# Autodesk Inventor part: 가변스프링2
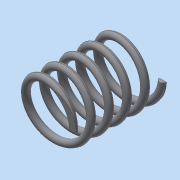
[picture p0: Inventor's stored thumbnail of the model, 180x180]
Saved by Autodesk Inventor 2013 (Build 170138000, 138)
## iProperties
Created: 2018-10
Part Number: 가변스프링2
Material: 일반
Document SubType Name: Modeling
Designer: Administrator
Density: 1 g/cm^3
Author: Administrator
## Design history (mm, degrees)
sketch "스케치1"
  geometry: L1 (0, 0)-(0, 25.765); L2 (0, 0)-(8, 0); L3 (0, 25.765)-(8, 25.765); C1 r 1 at (8, 0)
  constraints: 6 end point, 1 centre point, 1 horizontal alignment, 1 parallel, 1 perpendicular, 1 vertical
  dimensions: "d0" = 25.76498 distance of L1.start L1.end (derived); "d1" = 2 diameter of C1; "d2" = 16 diameter of L2.end L1; "d3" = 8 distance of L1.end L3.end
feature "코일1" sketch "스케치1" pitch "d4" = 10; turns "d6" = 5; dims "d5" = 25.76498 (= d0), "d7" = 0, angle "d8" = 90 deg, angle "d9" = 90 deg, "d10" = 0, "d11" = 0
sketch "스케치2"
  geometry: L1 (25.765, 10)-(0, 10); L2 (0, 10)-(0, -10); L3 (0, -10)-(25.765, -10); L4 (25.765, -10)-(25.765, 10); 2 further points
  constraints: 8 end point, 2 parallel, 1 coincident, 1 horizontal, 1 midpoint, 1 perpendicular
  dimensions: "d12" = 20 distance of L1.end L2.end; "d14" = 25.76498 distance of L2.end L3.end (derived)
extrude "돌출1" sketch "스케치2" stored distance "d15" = 0; taper "d16" = 0 deg
node "솔리드1"
